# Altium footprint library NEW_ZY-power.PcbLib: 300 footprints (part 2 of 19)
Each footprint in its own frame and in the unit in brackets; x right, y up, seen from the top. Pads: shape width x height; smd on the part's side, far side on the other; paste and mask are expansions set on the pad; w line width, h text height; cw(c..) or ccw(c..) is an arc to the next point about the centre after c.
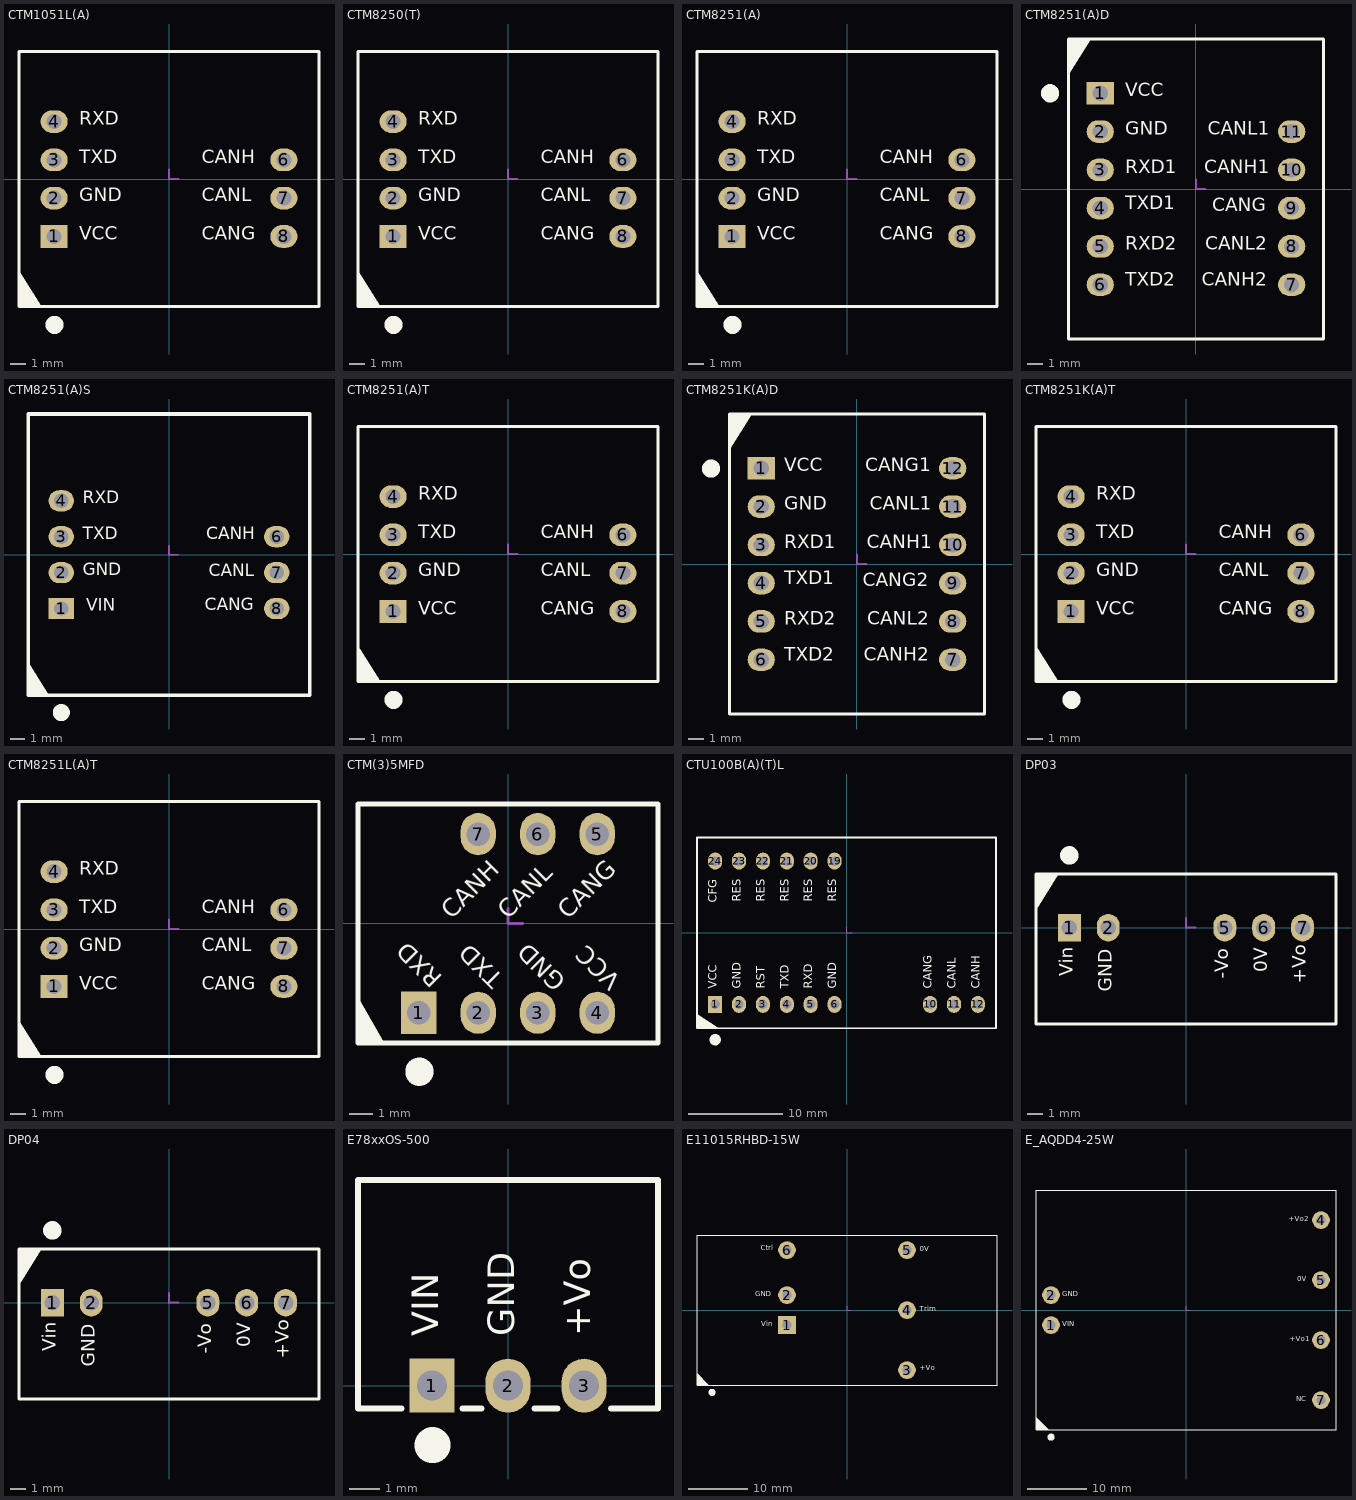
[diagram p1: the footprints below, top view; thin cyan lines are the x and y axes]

## CTM1051L(A) [mm]
height 7.1
pads (7):
  rect 1.8x1.5 hole 1: 1(-7.62,-3.81)
  oval 1.8x1.5 hole 1: 2(-7.62,-1.27) 3(-7.62,1.27) 4(-7.62,3.81) 6(7.62,1.27) 7(7.62,-1.27) 8(7.62,-3.81)
Top Overlay:
  circle w1: c-7.593,-9.675 r0.1
  region: -9.95,-6.12 -9.95,-8.45 -8.49,-8.45
  lines w0.2: -9.95,-8.45 -9.95,8.45 9.95,8.45 9.95,-8.45 -9.95,-8.45
  text "VCC" at -5.938,-4.318 h1.52
  text "RXD" at -5.939,3.302 h1.52
  text "TXD" at -5.939,0.762 h1.52
  text "GND" at -5.939,-1.778 h1.52
  text "CANH" at 2.189,0.762 h1.52
  text "CANL" at 2.189,-1.778 h1.52
  text "CANG" at 2.189,-4.318 h1.52
Mechanical 15:
  lines w0.127: 0,0.635 0,0 0.635,0

## CTM8250(T) [mm]
height 7.1
pads (7):
  rect 1.8x1.5 hole 1: 1(-7.62,-3.81)
  oval 1.8x1.5 hole 1: 2(-7.62,-1.27) 3(-7.62,1.27) 4(-7.62,3.81) 6(7.62,1.27) 7(7.62,-1.27) 8(7.62,-3.81)
Top Overlay:
  circle w1: c-7.593,-9.675 r0.1
  region: -9.95,-6.12 -9.95,-8.45 -8.49,-8.45
  lines w0.2: -9.95,-8.45 -9.95,8.45 9.95,8.45 9.95,-8.45 -9.95,-8.45
  text "VCC" at -5.938,-4.318 h1.52
  text "RXD" at -5.939,3.302 h1.52
  text "TXD" at -5.939,0.762 h1.52
  text "GND" at -5.939,-1.778 h1.52
  text "CANH" at 2.189,0.762 h1.52
  text "CANL" at 2.189,-1.778 h1.52
  text "CANG" at 2.189,-4.318 h1.52
Mechanical 15:
  lines w0.127: 0,0.635 0,0 0.635,0

## CTM8251(A) [mm]
height 7.1
pads (7):
  rect 1.8x1.5 hole 1: 1(-7.62,-3.81)
  oval 1.8x1.5 hole 1: 2(-7.62,-1.27) 3(-7.62,1.27) 4(-7.62,3.81) 6(7.62,1.27) 7(7.62,-1.27) 8(7.62,-3.81)
Top Overlay:
  circle w1: c-7.593,-9.673 r0.1
  region: -9.95,-6.12 -9.95,-8.45 -8.49,-8.45
  lines w0.2: -9.95,-8.45 9.95,-8.45 9.95,8.45 -9.95,8.45 -9.95,-8.45
  text "CANG" at 2.189,-4.318 h1.52
  text "CANL" at 2.189,-1.778 h1.52
  text "CANH" at 2.189,0.762 h1.52
  text "GND" at -5.939,-1.778 h1.52
  text "TXD" at -5.939,0.762 h1.52
  text "RXD" at -5.969,3.302 h1.52
  text "VCC" at -5.938,-4.318 h1.52
Mechanical 15:
  lines w0.127: 0,0.635 0,0 0.635,0

## CTM8251(A)D [mm]
height 7.05
pads (11):
  rect 1.8x1.5 hole 1: 1(-6.35,6.35)
  oval 1.8x1.5 hole 1: 2(-6.35,3.81) 3(-6.35,1.27) 4(-6.35,-1.27) 5(-6.35,-3.81) 6(-6.35,-6.35) 7(6.35,-6.35) 8(6.35,-3.81) 9(6.35,-1.27) 10(6.35,1.27) 11(6.35,3.81)
Top Overlay:
  circle w1: c-9.673,6.35 r0.1
  region: -8.45,7.62 -8.45,9.95 -6.99,9.95
  lines w0.2: -8.45,-9.95 -8.45,9.95 8.45,9.95 8.45,-9.95 -8.45,-9.95
  text "RXD2" at -4.699,-4.318 h1.52
  text "TXD2" at -4.699,-6.731 h1.52
  text "CANH2" at 0.381,-6.731 h1.52
  text "CANL2" at 0.607,-4.318 h1.52
  text "TXD1" at -4.699,-1.651 h1.52
  text "RXD1" at -4.699,0.762 h1.52
  text "GND" at -4.699,3.302 h1.52
  text "VCC" at -4.698,5.842 h1.52
  text "CANL1" at 0.785,3.302 h1.52
  text "CANH1" at 0.559,0.762 h1.52
  text "CANG" at 1.076,-1.778 h1.52
Mechanical 15:
  lines w0.127: 0,0.635 0,0 0.635,0

## CTM8251(A)S [mm]
height 5
pads (7):
  rect 1.8x1.5 hole 1: 1(-7.62,-3.81)
  oval 1.8x1.5 hole 1: 2(-7.62,-1.27) 3(-7.62,1.27) 4(-7.62,3.81) 6(7.62,1.27) 7(7.62,-1.27) 8(7.62,-3.81)
Top Overlay:
  circle w1: c-7.62,-11.173 r0.1
  region: -9.95,-7.62 -9.95,-9.95 -8.49,-9.95
  lines w0.254: -9.95,-9.95 9.95,-9.95 9.95,9.95 -9.95,9.95 -9.95,-9.95
  text "VIN" at -5.867,-4.293 h1.52
  text "GND" at -6.096,-1.761 h1.52
  text "TXD" at -6.096,0.77 h1.52
  text "RXD" at -6.096,3.302 h1.52
  text "CANH" at 2.641,0.762 h1.52
  text "CANL" at 2.806,-1.854 h1.52
  text "CANG" at 2.54,-4.267 h1.52
Mechanical 15:
  lines w0.127: 0,0.635 0,0 0.635,0

## CTM8251(A)T [mm]
height 7.1
pads (7):
  rect 1.8x1.5 hole 1: 1(-7.62,-3.81)
  oval 1.8x1.5 hole 1: 2(-7.62,-1.27) 3(-7.62,1.27) 4(-7.62,3.81) 6(7.62,1.27) 7(7.62,-1.27) 8(7.62,-3.81)
Top Overlay:
  circle w1: c-7.593,-9.675 r0.1
  region: -9.95,-6.223 -9.95,-8.45 -8.49,-8.45 -9.838,-6.298
  lines w0.2: -9.95,-8.45 9.95,-8.45 9.95,8.45 -9.95,8.45 -9.95,-8.45
  text "CANG" at 2.189,-4.318 h1.52
  text "CANL" at 2.189,-1.778 h1.52
  text "CANH" at 2.189,0.762 h1.52
  text "GND" at -5.939,-1.778 h1.52
  text "TXD" at -5.939,0.762 h1.52
  text "RXD" at -5.969,3.302 h1.52
  text "VCC" at -5.938,-4.318 h1.52
Mechanical 15:
  lines w0.127: 0,0.635 0,0 0.635,0

## CTM8251K(A)D [mm]
height 7.1
pads (12):
  rect 1.8x1.5 hole 1: 1(-6.35,6.35)
  oval 1.8x1.5 hole 1: 2(-6.35,3.81) 3(-6.35,1.27) 4(-6.35,-1.27) 5(-6.35,-3.81) 6(-6.35,-6.35) 7(6.35,-6.35) 8(6.35,-3.81) 9(6.35,-1.27) 10(6.35,1.27) 11(6.35,3.81) 12(6.35,6.35)
Top Overlay:
  circle w1: c-9.675,6.323 r0.1
  region: -8.45,7.62 -8.45,9.95 -6.99,9.95
  lines w0.2: -8.45,-9.95 -8.45,9.95 8.45,9.95 8.45,-9.95 -8.45,-9.95
  text "RXD2" at -4.827,-4.318 h1.52
  text "TXD2" at -4.827,-6.731 h1.52
  text "CANH2" at 0.457,-6.731 h1.52
  text "CANL2" at 0.683,-4.318 h1.52
  text "TXD1" at -4.827,-1.651 h1.52
  text "RXD1" at -4.827,0.762 h1.52
  text "GND" at -4.827,3.302 h1.52
  text "VCC" at -4.826,5.842 h1.52
  text "CANL1" at 0.861,3.302 h1.52
  text "CANH1" at 0.635,0.762 h1.52
  text "CANG2" at 0.381,-1.778 h1.52
  text "CANG1" at 0.559,5.842 h1.52
Mechanical 15:
  lines w0.127: 0,0.635 0,0 0.635,0

## CTM8251K(A)T [mm]
height 7.1
pads (7):
  rect 1.8x1.5 hole 1: 1(-7.62,-3.81)
  oval 1.8x1.5 hole 1: 2(-7.62,-1.27) 3(-7.62,1.27) 4(-7.62,3.81) 6(7.62,1.27) 7(7.62,-1.27) 8(7.62,-3.81)
Top Overlay:
  circle w1: c-7.593,-9.675 r0.1
  region: -9.95,-6.223 -9.95,-8.45 -8.49,-8.45 -9.838,-6.298
  lines w0.2: -9.95,-8.45 -9.95,8.45 9.95,8.45 9.95,-8.45 -9.95,-8.45
  text "CANG" at 2.189,-4.318 h1.52
  text "CANL" at 2.189,-1.778 h1.52
  text "CANH" at 2.189,0.762 h1.52
  text "GND" at -5.939,-1.778 h1.52
  text "TXD" at -5.939,0.762 h1.52
  text "RXD" at -5.969,3.302 h1.52
  text "VCC" at -5.938,-4.318 h1.52
Mechanical 15:
  lines w0.127: 0,0.635 0,0 0.635,0

## CTM8251L(A)T [mm]
height 7.1
pads (7):
  rect 1.8x1.5 hole 1: 1(-7.62,-3.81)
  oval 1.8x1.5 hole 1: 2(-7.62,-1.27) 3(-7.62,1.27) 4(-7.62,3.81) 6(7.62,1.27) 7(7.62,-1.27) 8(7.62,-3.81)
Top Overlay:
  circle w1: c-7.593,-9.675 r0.1
  region: -9.95,-6.12 -9.95,-8.45 -8.49,-8.45
  lines w0.2: -9.95,-8.45 9.95,-8.45 9.95,8.45 -9.95,8.45 -9.95,-8.45
  text "CANG" at 2.189,-4.318 h1.52
  text "CANL" at 2.189,-1.778 h1.52
  text "CANH" at 2.189,0.762 h1.52
  text "GND" at -5.939,-1.778 h1.52
  text "TXD" at -5.939,0.762 h1.52
  text "RXD" at -5.969,3.302 h1.52
  text "VCC" at -5.938,-4.318 h1.52
Mechanical 15:
  lines w0.127: 0,0.635 0,0 0.635,0

## CTM(3)5MFD [mm]
height 7.7
pads (7):
  rect 1.5x1.8 hole 1: 1(-3.81,-3.81)
  oval 1.5x1.8 hole 1: 2(-1.27,-3.81) 3(1.27,-3.81) 4(3.81,-3.81) 5(3.81,3.81) 6(1.27,3.81) 7(-1.27,3.81)
Top Overlay:
  circle w1: c-3.783,-6.325 r0.1
  region: -5.284,-5.1 -6.4,-3.161 -6.4,-5.1
  lines w0.2: -6.4,-5.1 -6.4,5.1 6.4,5.1 6.4,-5.1 -6.4,-5.1
  text "CANG" at 2.748,-0.025 h1.27
  text "CANL" at 0.178,-0.025 h1.27
  text "CANH" at -2.235,-0.025 h1.27
  text "VCC" at 5.055,-2.214 h1.27
  text "GND" at 2.692,-2.252 h1.27
  text "TXD" at 0.025,-2.113 h1.27
  text "RXD" at -2.565,-2.108 h1.27
Mechanical 15:
  lines w0.127: 0,0.635 0,0 0.635,0

## CTU100B(A)(T)L [mm]
height 6.5
pads (15):
  rect 1.5x1.8 hole 1: 1(-13.97,-7.62)
  oval 1.5x1.8 hole 1: 2(-11.43,-7.62) 3(-8.89,-7.62) 4(-6.35,-7.62) 5(-3.81,-7.62) 6(-1.27,-7.62) 10(8.89,-7.62) 11(11.43,-7.62) 12(13.97,-7.62) 19(-1.27,7.62) 20(-3.81,7.62) 21(-6.35,7.62) 22(-8.89,7.62) 23(-11.43,7.62) 24(-13.97,7.62)
Top Overlay:
  circle w1: c-13.97,-11.375 r0.1
  region: -13.57,-10.15 -15.9,-10.15 -15.9,-8.69
  lines w0.2: -15.9,-10.15 -15.9,10.15 15.9,10.15 15.9,-10.15 -15.9,-10.15
  text "VCC" at -13.462,-5.969 h1.52
  text "GND" at -10.922,-5.969 h1.52
  text "RST" at -8.382,-5.969 h1.52
  text "TXD" at -5.842,-5.969 h1.52
  text "RXD" at -3.302,-5.969 h1.52
  text "GND" at -0.762,-5.969 h1.52
  text "CANG" at 9.398,-5.969 h1.52
  text "CANL" at 11.938,-5.969 h1.52
  text "CANH" at 14.478,-5.969 h1.52
  text "CFG" at -13.462,3.192 h1.52
  text "RES" at -10.922,3.29 h1.52
  text "RES" at -8.382,3.29 h1.52
  text "RES" at -5.842,3.29 h1.52
  text "RES" at -3.302,3.29 h1.52
  text "RES" at -0.762,3.29 h1.52
Mechanical 15:
  lines w0.127: 0,0.635 0,0 0.635,0

## DP03 [mm]
height 12.5
pads (5):
  rect 1.5x1.8 hole 1: 1(-7.62,0)
  oval 1.5x1.8 hole 1: 2(-5.08,0) 5(2.533,0) 6(5.073,0) 7(7.62,0)
Top Overlay:
  circle w1: c-7.62,4.725 r0.1
  region: -9.8,1.17 -9.8,3.5 -8.34,3.5
  lines w0.2: -9.8,-6.3 9.8,-6.3 9.8,3.5 -9.8,3.5 -9.8,-6.3
  text "0V" at 5.588,-2.909 h1.52
  text "+Vo" at 8.128,-3.649 h1.52
  text "-Vo" at 3.048,-3.337 h1.52
  text "GND" at -4.572,-4.191 h1.52
  text "Vin" at -7.112,-3.181 h1.52
Mechanical 15:
  lines w0.127: 0,0.635 0,0 0.635,0

## DP04 [mm]
height 12.5
pads (5):
  rect 1.5x1.8 hole 1: 1(-7.62,0)
  oval 1.5x1.8 hole 1: 2(-5.08,0) 5(2.533,0) 6(5.073,0) 7(7.62,0)
Top Overlay:
  circle w1: c-7.62,4.725 r0.1
  region: -9.8,1.17 -9.8,3.5 -8.34,3.5
  lines w0.2: -9.8,-6.3 9.8,-6.3 9.8,3.5 -9.8,3.5 -9.8,-6.3
  text "0V" at 5.588,-2.909 h1.52
  text "+Vo" at 8.128,-3.649 h1.52
  text "-Vo" at 3.048,-3.337 h1.52
  text "GND" at -4.572,-4.191 h1.52
  text "Vin" at -7.112,-3.181 h1.52
Mechanical 15:
  lines w0.127: 0,0.635 0,0 0.635,0

## E78xxOS-500 [mm]
height 11
pads (3):
  rect 1.5x1.8 hole 1: 1(-2.54,0)
  oval 1.5x1.8 hole 1: 2(0,0) 3(2.54,0)
Top Overlay:
  circle w1: c-2.513,-1.987 r0.1
  lines w0.2: -3.556,-0.762 -5,-0.762 -5,6.858 5,6.858 5,-0.762 3.429,-0.762 ; -1.524,-0.762 -0.889,-0.762 ; 0.889,-0.762 1.651,-0.762
  text "+Vo" at 3.048,1.651 h1.52
  text "GND" at 0.508,1.651 h1.52
  text "VIN" at -2.032,1.651 h1.52
Mechanical 15:
  lines w0.127: 0,0.635 0,0 0.635,0

## E11015RHBD-15W [mm]
height 12.7
pads (6):
  rect 3x3 hole 1.5: 1(-10.16,-2.54)
  round 3 hole 1.5: 2(-10.16,2.54) 3(10.16,-10.16) 4(10.16,0) 5(10.16,10.16) 6(-10.16,10.16)
Top Overlay:
  circle w1: c-22.86,-13.925 r0.1
  region: -25.4,-12.7 -23.425,-12.7 -25.4,-10.725
  lines w0.2: -25.4,-12.7 -25.4,12.7 25.4,12.7 25.4,-12.7 -25.4,-12.7
  text "+Vo" at 12.319,-10.541 h1.52
  text "0V" at 12.319,9.652 h1.52
  text "GND" at -15.495,2.032 h1.52
  text "Vin" at -14.485,-3.048 h1.52
  text "Trim" at 12.319,-0.508 h1.52
  text "Ctrl" at -14.57,9.779 h1.52
Mechanical 15:
  lines w0.127: 0,0.635 0,0 0.635,0

## E_AQDD4-25W [mm]
height 13.8
pads (6):
  round 3 hole 1.5: 1(-22.86,-2.54) 2(-22.86,2.54) 4(22.86,15.24) 5(22.86,5.08) 6(22.86,-5.08) 7(22.86,-15.24)
Top Overlay:
  circle w1: c-22.86,-21.525 r0.1
  region: -25.298,-20.203 -23.323,-20.203 -25.298,-18.228
  lines w0.2: -25.4,-20.3 -25.4,20.3 0,20.3 25.4,20.3 25.4,-20.3 -25.4,-20.3
  text "VIN" at -20.955,-3.048 h1.52
  text "GND" at -20.955,2.032 h1.52
  text "0V" at 18.876,4.572 h1.52
  text "+Vo2" at 17.399,14.732 h1.52
  text "+Vo1" at 17.577,-5.588 h1.52
  text "NC" at 18.665,-15.748 h1.52
Mechanical 15:
  lines w0.127: 0,0.635 0,0 0.635,0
